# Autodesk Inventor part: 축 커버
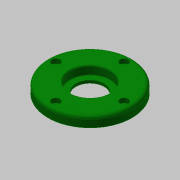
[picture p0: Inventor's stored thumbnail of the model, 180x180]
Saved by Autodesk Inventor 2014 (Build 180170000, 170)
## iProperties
Created: 2015-10
Part Number: 축 커버
Document SubType Name: Modeling
Designer: mdu
Density: 1 g/cm^3
Material: 일반
Appearance: 진녹색
Author: mdu
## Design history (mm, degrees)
sketch "스케치1"
  geometry: C1 r 40 at (0, 0) reference; C2 r 26 at (0, 0) reference; 1 further point
  node "참조1"
  node "참조2"
extrude "돌출1" new body sketch "스케치1" distance "d0" = 10; taper "d1" = 0 deg
extrude "돌출2" join sketch "스케치1" distance "d2" = 4; taper "d3" = 0 deg
hole "구멍1" diameter "d6" = 27; stored, may be unused: countersink angle "d10" = 90 deg, drill point angle "d12" = 118 deg; dims "d7" = 6, "d8" = 38, "d9" = 8.3, "d11" = 8, "d33" = 10, "d34" = 10
sketch "스케치2"
  geometry: C1 r 20 at (0, 0); 1 further point
  constraints: 1 centre point, 1 coincident
  dimensions: "d13" = 40 diameter of C1
extrude "돌출3" cut sketch "스케치2" distance "d14" = 3; taper "d15" = 0 deg
sketch "스케치3"
  geometry: C1 r 1.621 at (0, 32.5) reference; 1 further point
hole "구멍2" sketch "스케치3" at (0, 32.5) diameter "d16" = 4.5; stored, may be unused: countersink angle "d20" = 90 deg, drill point angle "d22" = 118 deg; dims "d17" = 6, "d18" = 8, "d19" = 4.4, "d21" = 8
fillet "모깎기1" dims "d26" = 3, "d27" = 0.3
chamfer "모따기1" distance "d28" = 1; stored, may be unused: second distance "d29" = 2, angle "d30" = 45 deg
chamfer "모따기2" distance "d31" = 0.8; stored, may be unused: second distance "d32" = 2, angle "d35" = 30 deg
node "솔리드1"
pattern_circular "원형 패턴1" dims angle "d24" = 360 deg
node "참조3"
